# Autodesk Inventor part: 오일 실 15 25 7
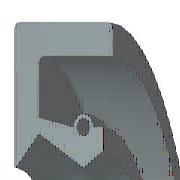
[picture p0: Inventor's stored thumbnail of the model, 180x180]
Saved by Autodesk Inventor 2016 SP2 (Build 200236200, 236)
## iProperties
Created: 2012-02
Part Number: 오일 실 15 25 7
Material: 고무
Description: 오일-실
Document SubType Name: Modeling
Standard: KS B 2804
Designer: mduedu
Standards Organization: KS
Language: ko-KR
Size Designation: D - 15 25 7
Categories: <MemberInstance><Categories><Category DisplayName="샤프트 부품" InternalName="7f7aeb1f-a693-4053-b835-cee3144e0d98" Mnemonic="SHFT"><Category DisplayName="실링" Intern
Density: 0.93 g/cm^3
Appearance: 고무 - 검은색 - 버전 1.1
IsCustomPart: 1
Author: mduedu
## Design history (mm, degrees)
revolve "본체" stored, may be unused: angle "d17" = 90 deg
revolve "스프링1" stored, may be unused: angle "d18" = 90 deg
body "Solid1"
sketch "스케치1"
  geometry: L1 (0, 12.5)-(7, 12.5); L2 (7, 10.75)-(1.75, 10.75); L3 (1.75, 9.25)-(4.9, 7.5); L4 (4.9, 7.5)-(0, 7.5); L5 (0, 0)-(9.586, 0) reference; L6 (4.9, 7.5)-(6.3, 8.375); L7 (0, 18)-(0, -3) reference; L8 (-1.941, 0)-(11.507, 0) reference; L9 (4.2, 9.6)-(1.75, 10.09); L10 (1.75, 10.09)-(1.75, 10.75); L11 (0, 12.5)-(0, 7.588); L12 (4.9, 7.5)-(0, 7.5); L13 (1.75, 9.25)-(0.152, 7.528); L14 (7, 12.5)-(7, 10.75); L15 (5.6, 9.6)-(6.3, 9.6); L16 (6.3, 9.6)-(6.3, 8.375); C1 r 0.455 at (4.9, 9.6); A1 r 0.7 centre (4.9, 9.6) between (5.6, 9.6) and (4.2, 9.6); A2 r 0.088 centre (0.088, 7.588) between (0, 7.588) and (0.152, 7.528); 1 further point
  constraints: 28 end point, 5 horizontal alignment, 5 point on line, 4 point on circle, 4 vertical alignment, 3 centre point, 3 tangent, 2 collinear, 2 horizontal, 2 perpendicular, 1 coincident, 1 parallel
  dimensions: "d0" = 25 diameter of L1 L5 (= SD2); "d1" = 1.75 distance of L1.end L2.start (= SD); "d2" = 0.91 diameter of C1 (= SPDI); "d3" = 1.4 diameter of A1 (= SPDA); "d4" = 15 diameter of L3.end L5 (= NND); "d5" = 18.5 diameter of L3.start L5 (= TKDM); "d7" = 20.18 diameter of L9.end L5 (= TKDM + 0.24 x SWDT); "d8" = 1.75 distance between parallel lines of L11 L10 (= SD); "d9" = 4.9 distance from line of L11 C1.centre (= SPDST); "d10" = 19.2 diameter of C1.centre L5 (= HLDM); "d11" = 0.0875 radius of A2 (= 0.25 x LAB); "d12" = 6.3 distance between parallel lines of L11 L16 (= SDI); "d13" = 16.75 diameter of L6.end L5 (= ABDM); "d14" = 7 distance from line of L11 L1.end (= SWDT)
fillet "모깎기1" dims "d6" = 0.3 (= RR)
other parameters: "SD2" = 25 [user parameter; used in 1 equation term], "SWDT" = 7 [user parameter; used in 2 equation terms], "RR" = 0.3 [user parameter; used in 1 equation term], "SD" = 1.75 [user parameter; used in 2 equation terms], "NND" = 15 [user parameter; used in 1 equation term], "SPDA" = 1.4 [user parameter; used in 1 equation term], "SPDI" = 0.91 [user parameter; used in 1 equation term], "TKDM" = 18.5 [user parameter; used in 2 equation terms], "HLDM" = 19.2 [user parameter; used in 1 equation term], "ABDM" = 16.75 [user parameter; used in 1 equation term], "SDI" = 6.3 [user parameter; used in 1 equation term], "SPDST" = 4.9 [user parameter; used in 1 equation term], "LAB" = 0.35 [user parameter; used in 1 equation term], "d15" = 0, "d16" = 0, "d19" = 0
